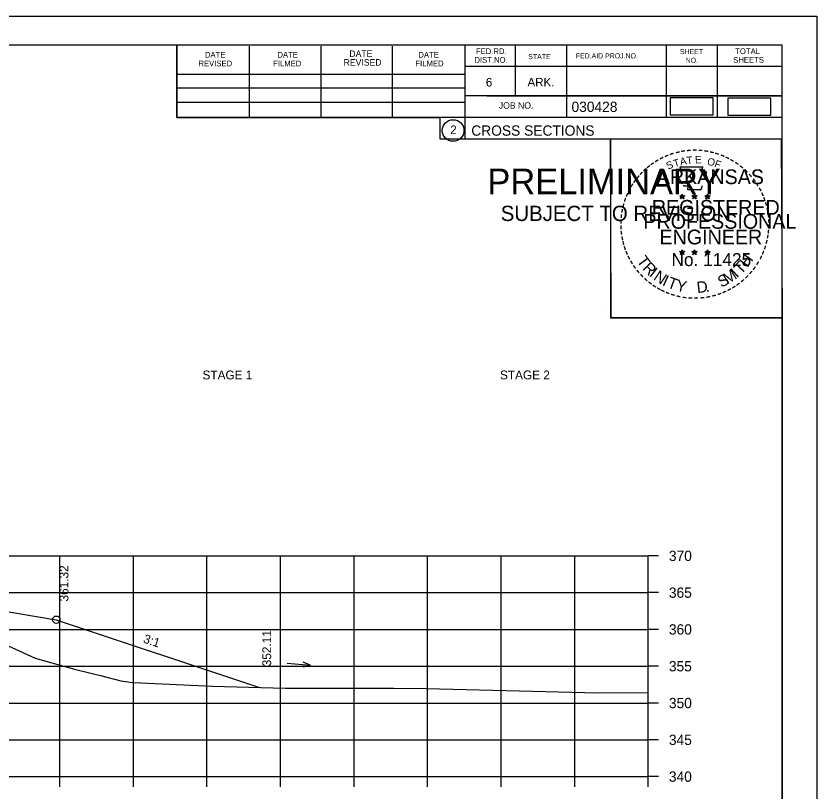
# Model space of a CAD drawing. Extents: x 1374859 to 1376773, y 382242 to 389804.
# Drawn here: x 1376188.6 to 1376297.5, y 385336.4 to 385441.8 of the extents above; entities that cross this region are included whole.
import ezdxf

# ---------------------------------------------------------------- set-up
doc = ezdxf.new("R2010")
doc.units = 0
for name, color, linetype in [('R_Axis', 7, 'Continuous'), ('R_Axis Annot', 7, 'Continuous'), ('R_Border', 7, 'Continuous'), ('R_Border PE', 7, 'Continuous'), ('R_Border Prem', 7, 'Continuous'), ('R_Exist Surface', 7, 'Continuous'), ('R_Fin Surface', 7, 'Continuous'), ('R_Grid', 7, 'Continuous'), ('R_MOT', 7, 'Continuous'), ('R_No Plot', 7, 'Continuous'), ('R_Water Annot', 7, 'Continuous'), ('R_Xsect Elev', 7, 'Continuous'), ('R_Xsect Slope', 7, 'Continuous')]:
    doc.layers.add(name, color=color, linetype=linetype)

msp = doc.modelspace()

# ---------------------------------------------------------------- linework, layer by layer
at = {"layer": 'R_Axis'}
for p, q in [((1376274.57, 385338.45), (1376274.57, 385368.45)), ((1376275.97, 385368.45), (1376274.57, 385368.45)), ((1376275.97, 385363.45), (1376274.57, 385363.45)), ((1376275.97, 385358.45), (1376274.57, 385358.45)), ((1376275.97, 385353.45), (1376274.57, 385353.45)), ((1376275.97, 385348.45), (1376274.57, 385348.45)), ((1376275.97, 385343.45), (1376274.57, 385343.45)), ((1375994.57, 385338.45), (1376274.57, 385338.45)), ((1376194.57, 385337.05), (1376194.57, 385338.45)), ((1376204.57, 385337.05), (1376204.57, 385338.45)), ((1376214.57, 385337.05), (1376214.57, 385338.45)), ((1376224.57, 385337.05), (1376224.57, 385338.45)), ((1376234.57, 385337.05), (1376234.57, 385338.45)), ((1376244.57, 385337.05), (1376244.57, 385338.45)), ((1376254.57, 385337.05), (1376254.57, 385338.45)), ((1376264.57, 385337.05), (1376264.57, 385338.45)), ((1376274.57, 385337.05), (1376274.57, 385338.45)), ((1376275.97, 385338.45), (1376274.57, 385338.45))]:
    msp.add_line(p, q, dxfattribs=at)
at = {"layer": 'R_Border'}
for p, q in [((1375976.57, 385437.91), (1376292.75, 385437.91)), ((1376210.49, 385428.03), (1376210.49, 385437.91)), ((1376220.35, 385428.03), (1376220.35, 385437.71)), ((1376230.11, 385428.03), (1376230.11, 385437.71)), ((1376239.79, 385428.03), (1376239.79, 385437.71)), ((1376249.65, 385437.91), (1376249.65, 385425.11)), ((1376256.49, 385437.91), (1376256.49, 385430.97)), ((1376263.43, 385437.91), (1376263.43, 385428.03)), ((1376277.01, 385437.91), (1376277.01, 385428.03)), ((1376283.95, 385437.91), (1376283.95, 385428.03)), ((1376292.75, 385232.45), (1376292.75, 385437.91)), ((1376292.75, 385434.97), (1376249.65, 385434.97)), ((1376292.75, 385434.99), (1376292.75, 385434.99)), ((1376210.49, 385433.89), (1376249.65, 385433.89)), ((1376210.49, 385432.03), (1376249.65, 385432.03)), ((1376292.75, 385430.97), (1376249.65, 385430.97)), ((1376252.61, 385430.97), (1376292.75, 385430.97)), ((1376210.49, 385428.03), (1376210.49, 385430.09)), ((1376210.49, 385430.09), (1376249.65, 385430.09)), ((1376292.75, 385428.03), (1376210.49, 385428.03)), ((1376249.65, 385425.11), (1376292.75, 385425.11))]:
    msp.add_line(p, q, dxfattribs=at)
msp.add_circle((1376248.04, 385426.25), 1.47, dxfattribs=at)
at = {"layer": 'R_Border PE'}
for p, q in [((1376278.84, 385417.37), (1376279.18, 385417.26)), ((1376278.84, 385417.37), (1376279.09, 385417.32)), ((1376278.84, 385417.37), (1376279.07, 385417.25)), ((1376278.97, 385416.96), (1376279.18, 385417.26)), ((1376278.97, 385416.96), (1376279.09, 385417.2)), ((1376278.97, 385416.96), (1376279.18, 385417.18)), ((1376279.18, 385417.62), (1376279.14, 385417.37)), ((1376279.18, 385417.26), (1376279.18, 385417.62)), ((1376279.18, 385417.62), (1376279.23, 385417.37)), ((1376279.53, 385417.37), (1376279.18, 385417.26)), ((1376279.4, 385416.96), (1376279.18, 385417.26)), ((1376279.4, 385416.96), (1376279.18, 385417.17)), ((1376279.53, 385417.37), (1376279.25, 385417.32)), ((1376279.4, 385416.96), (1376279.26, 385417.25)), ((1376279.53, 385417.37), (1376279.33, 385417.27)), ((1376280.51, 385417.37), (1376280.85, 385417.26)), ((1376280.51, 385417.37), (1376280.76, 385417.32)), ((1376280.51, 385417.37), (1376280.74, 385417.25)), ((1376280.64, 385416.96), (1376280.85, 385417.26)), ((1376280.64, 385416.96), (1376280.76, 385417.2)), ((1376280.64, 385416.96), (1376280.85, 385417.18)), ((1376280.85, 385417.62), (1376280.81, 385417.37)), ((1376280.85, 385417.26), (1376280.85, 385417.62)), ((1376280.85, 385417.62), (1376280.9, 385417.37)), ((1376281.2, 385417.37), (1376280.85, 385417.26)), ((1376281.07, 385416.96), (1376280.85, 385417.26)), ((1376281.07, 385416.96), (1376280.85, 385417.17)), ((1376281.2, 385417.37), (1376280.92, 385417.32)), ((1376281.07, 385416.96), (1376280.93, 385417.25)), ((1376281.2, 385417.37), (1376281, 385417.27)), ((1376282.27, 385417.36), (1376282.62, 385417.24)), ((1376282.27, 385417.36), (1376282.52, 385417.31)), ((1376282.27, 385417.36), (1376282.51, 385417.23)), ((1376282.4, 385416.95), (1376282.62, 385417.24)), ((1376282.4, 385416.95), (1376282.53, 385417.19)), ((1376282.4, 385416.95), (1376282.62, 385417.16)), ((1376282.62, 385417.61), (1376282.58, 385417.36)), ((1376282.62, 385417.24), (1376282.62, 385417.61)), ((1376282.62, 385417.61), (1376282.67, 385417.36)), ((1376282.97, 385417.36), (1376282.62, 385417.24)), ((1376282.83, 385416.95), (1376282.62, 385417.24)), ((1376282.83, 385416.95), (1376282.62, 385417.16)), ((1376282.97, 385417.36), (1376282.68, 385417.31)), ((1376282.83, 385416.95), (1376282.69, 385417.24)), ((1376282.97, 385417.36), (1376282.76, 385417.25)), ((1376279.18, 385410.05), (1376279.14, 385409.8)), ((1376279.18, 385409.68), (1376279.18, 385410.05)), ((1376279.18, 385410.05), (1376279.23, 385409.8)), ((1376280.85, 385410.05), (1376280.81, 385409.8)), ((1376280.85, 385409.68), (1376280.85, 385410.05)), ((1376280.85, 385410.05), (1376280.9, 385409.8)), ((1376282.62, 385410.04), (1376282.58, 385409.79)), ((1376282.62, 385409.67), (1376282.62, 385410.04)), ((1376282.62, 385410.04), (1376282.67, 385409.79)), ((1376278.83, 385409.79), (1376279.18, 385409.68)), ((1376278.83, 385409.79), (1376279.08, 385409.75)), ((1376278.83, 385409.79), (1376279.07, 385409.67)), ((1376278.96, 385409.39), (1376279.18, 385409.68)), ((1376278.96, 385409.39), (1376279.09, 385409.63)), ((1376278.96, 385409.39), (1376279.18, 385409.6)), ((1376279.53, 385409.79), (1376279.18, 385409.68)), ((1376279.39, 385409.39), (1376279.18, 385409.68)), ((1376279.39, 385409.39), (1376279.18, 385409.6)), ((1376279.53, 385409.79), (1376279.24, 385409.75)), ((1376279.39, 385409.39), (1376279.26, 385409.68)), ((1376279.53, 385409.79), (1376279.32, 385409.69)), ((1376280.5, 385409.79), (1376280.85, 385409.68)), ((1376280.5, 385409.79), (1376280.75, 385409.75)), ((1376280.5, 385409.79), (1376280.74, 385409.67)), ((1376280.63, 385409.39), (1376280.85, 385409.68)), ((1376280.63, 385409.39), (1376280.76, 385409.63)), ((1376280.63, 385409.39), (1376280.85, 385409.6)), ((1376281.2, 385409.79), (1376280.85, 385409.68)), ((1376281.06, 385409.39), (1376280.85, 385409.68)), ((1376281.06, 385409.39), (1376280.85, 385409.6)), ((1376281.2, 385409.79), (1376280.91, 385409.75)), ((1376281.06, 385409.39), (1376280.93, 385409.68)), ((1376281.2, 385409.79), (1376280.99, 385409.69)), ((1376282.27, 385409.78), (1376282.62, 385409.67)), ((1376282.27, 385409.78), (1376282.52, 385409.74)), ((1376282.27, 385409.78), (1376282.5, 385409.66)), ((1376282.4, 385409.38), (1376282.62, 385409.67)), ((1376282.4, 385409.38), (1376282.53, 385409.62)), ((1376282.4, 385409.38), (1376282.61, 385409.59)), ((1376282.83, 385409.38), (1376282.61, 385409.59)), ((1376282.96, 385409.78), (1376282.62, 385409.67)), ((1376282.83, 385409.38), (1376282.62, 385409.67)), ((1376282.96, 385409.78), (1376282.68, 385409.74)), ((1376282.83, 385409.38), (1376282.69, 385409.67)), ((1376282.96, 385409.78), (1376282.76, 385409.68))]:
    msp.add_line(p, q, dxfattribs=at)
for points in [[(1376278.88, 385421.25), (1376279.15, 385420.42)], [(1376282.39, 385420.32), (1376282.53, 385420.61), (1376281.84, 385420.58), (1376281.99, 385421.25), (1376278.88, 385421.25)], [(1376279.37, 385418.82), (1376279.37, 385418.74), (1376279.93, 385418.72), (1376279.88, 385418.24), (1376281.75, 385418.24), (1376281.95, 385418.78)], [(1376279.18, 385417.62), (1376279.4, 385416.96), (1376278.84, 385417.37), (1376279.53, 385417.37), (1376278.97, 385416.96), (1376279.18, 385417.62)], [(1376280.85, 385417.62), (1376281.07, 385416.96), (1376280.51, 385417.37), (1376281.2, 385417.37), (1376280.64, 385416.96), (1376280.85, 385417.62)], [(1376282.62, 385417.61), (1376282.83, 385416.95), (1376282.27, 385417.36), (1376282.97, 385417.36), (1376282.4, 385416.95), (1376282.62, 385417.61)], [(1376279.18, 385410.05), (1376279.39, 385409.39), (1376278.83, 385409.79), (1376279.53, 385409.79), (1376278.96, 385409.39), (1376279.18, 385410.05)], [(1376280.85, 385410.05), (1376281.06, 385409.39), (1376280.5, 385409.79), (1376281.2, 385409.79), (1376280.63, 385409.39), (1376280.85, 385410.05)], [(1376282.62, 385410.04), (1376282.83, 385409.38), (1376282.27, 385409.78), (1376282.96, 385409.78), (1376282.4, 385409.38), (1376282.62, 385410.04)]]:
    msp.add_lwpolyline(points, dxfattribs=at)
for centre, radius in [((1376279.18, 385417.26), 0.172), ((1376279.18, 385417.26), 0.145), ((1376279.18, 385417.26), 0.116), ((1376279.18, 385417.26), 0.0991), ((1376279.18, 385417.26), 0.0747), ((1376279.18, 385417.26), 0.0495), ((1376279.18, 385417.26), 0.0296), ((1376280.85, 385417.26), 0.172), ((1376280.85, 385417.26), 0.145), ((1376280.85, 385417.26), 0.116), ((1376280.85, 385417.26), 0.0991), ((1376280.85, 385417.26), 0.0747), ((1376280.85, 385417.26), 0.0495), ((1376280.85, 385417.26), 0.0296), ((1376282.62, 385417.24), 0.172), ((1376282.62, 385417.24), 0.145), ((1376282.62, 385417.24), 0.116), ((1376282.62, 385417.24), 0.0991), ((1376282.62, 385417.24), 0.0747), ((1376282.62, 385417.24), 0.0495), ((1376282.62, 385417.24), 0.0296), ((1376279.18, 385409.68), 0.172), ((1376279.18, 385409.68), 0.145), ((1376279.18, 385409.68), 0.116), ((1376279.18, 385409.68), 0.0991), ((1376279.18, 385409.68), 0.0747), ((1376279.18, 385409.68), 0.0495), ((1376279.18, 385409.68), 0.0296), ((1376280.85, 385409.68), 0.172), ((1376280.85, 385409.68), 0.145), ((1376280.85, 385409.68), 0.116), ((1376280.85, 385409.68), 0.0991), ((1376280.85, 385409.68), 0.0747), ((1376280.85, 385409.68), 0.0495), ((1376280.85, 385409.68), 0.0296), ((1376282.62, 385409.67), 0.172), ((1376282.62, 385409.67), 0.145), ((1376282.62, 385409.67), 0.116), ((1376282.62, 385409.67), 0.0991), ((1376282.62, 385409.67), 0.0747), ((1376282.62, 385409.67), 0.0495), ((1376282.62, 385409.67), 0.0296)]:
    msp.add_circle(centre, radius, dxfattribs=at)
at = {"layer": 'R_Exist Surface'}
msp.add_lwpolyline([(1376175.15, 385361.82), (1376189.02, 385355.56), (1376191.23, 385354.54), (1376196.57, 385353.07), (1376198.96, 385352.47), (1376200.11, 385352.19), (1376202.87, 385351.46), (1376204.15, 385351.28), (1376204.59, 385351.24), (1376215.33, 385350.75), (1376225.21, 385350.47), (1376239.93, 385350.46), (1376244.36, 385350.44), (1376258.82, 385350.05), (1376267.71, 385349.83), (1376274.57, 385349.87)], dxfattribs=at)
at = {"layer": 'R_Fin Surface'}
msp.add_lwpolyline([(1376045.72, 385350.21), (1376053.8, 385347.51), (1376075.09, 385354.61), (1376084.29, 385356.14), (1376097.09, 385358.27), (1376105.09, 385358.82), (1376134.59, 385360.86), (1376164.09, 385362.89), (1376172.09, 385363.44), (1376185.45, 385361.21), (1376194.09, 385359.77), (1376221.71, 385350.57)], dxfattribs=at)
at = {"layer": 'R_Grid'}
for p, q in [((1375994.57, 385368.45), (1376274.57, 385368.45)), ((1376194.57, 385338.45), (1376194.57, 385368.45)), ((1376204.57, 385338.45), (1376204.57, 385368.45)), ((1376214.57, 385338.45), (1376214.57, 385368.45)), ((1376224.57, 385338.45), (1376224.57, 385368.45)), ((1376234.57, 385338.45), (1376234.57, 385368.45)), ((1376244.57, 385338.45), (1376244.57, 385368.45)), ((1376254.57, 385338.45), (1376254.57, 385368.45)), ((1376264.57, 385338.45), (1376264.57, 385368.45)), ((1376274.57, 385338.45), (1376274.57, 385368.45)), ((1375994.57, 385363.45), (1376274.57, 385363.45)), ((1375994.57, 385358.45), (1376274.57, 385358.45)), ((1375994.57, 385353.45), (1376274.57, 385353.45)), ((1375994.57, 385348.45), (1376274.57, 385348.45)), ((1375994.57, 385343.45), (1376274.57, 385343.45)), ((1375994.57, 385338.45), (1376274.57, 385338.45))]:
    msp.add_line(p, q, dxfattribs=at)
at = {"layer": 'R_MOT'}
for points in [[(1376277.55, 385428.37), (1376283.38, 385428.37), (1376283.38, 385430.68), (1376277.55, 385430.68)], [(1376285.38, 385428.35), (1376291.21, 385428.35), (1376291.21, 385430.66), (1376285.38, 385430.66)]]:
    msp.add_lwpolyline(points, close=True, dxfattribs=at)
at = {"layer": 'R_No Plot'}
for p, q in [((1375964.17, 385441.81), (1376297.5, 385441.81)), ((1376268.78, 385402.66), (1376268.78, 385402.66))]:
    msp.add_line(p, q, dxfattribs=at)
for points in [[(1375964.16, 385441.81), (1376297.5, 385441.81), (1376297.5, 385228.47), (1375964.16, 385228.47)], [(1376210.49, 385437.91), (1376210.49, 385428.03), (1376246.22, 385428.03), (1376246.22, 385425.11), (1376269.42, 385425.11), (1376269.42, 385400.78), (1376292.75, 385400.78), (1376292.75, 385232.45), (1375976.57, 385232.45), (1375976.57, 385437.91)], [(1376269.42, 385425.11), (1376292.63, 385425.11), (1376292.75, 385400.78), (1376269.54, 385400.78)]]:
    msp.add_lwpolyline(points, close=True, dxfattribs=at)
msp.add_circle((1376194.09, 385359.77), 0.5, dxfattribs=at)
at = {"layer": 'R_Water Annot'}
for p, q in [((1376225.46, 385353.88), (1376228.59, 385353.58)), ((1376228.59, 385353.58), (1376227.6, 385353.32)), ((1376228.59, 385353.58), (1376227.67, 385354.02))]:
    msp.add_line(p, q, dxfattribs=at)

# ---------------------------------------------------------------- texts
at = {"layer": 'R_Axis Annot'}
for s, p in [('STAGE 1', (1376213.97, 385392.43)), ('STAGE 2', (1376254.41, 385392.43))]:
    msp.add_text(s, height=1.2, rotation=360, dxfattribs=at).set_placement(p)
for s, p in [('370', (1376277.37, 385367.75)), ('365', (1376277.37, 385362.75)), ('360', (1376277.37, 385357.75)), ('355', (1376277.37, 385352.75)), ('350', (1376277.37, 385347.75)), ('345', (1376277.37, 385342.75)), ('340', (1376277.37, 385337.75))]:
    msp.add_text(s, height=1.4, dxfattribs=at).set_placement(p)
at = {"layer": 'R_Border'}
for s, height, p in [('FED.RD.', 0.782, (1376251.13, 385436.63)), ('SHEET', 0.684, (1376278.87, 385436.63)), ('TOTAL', 0.782, (1376286.39, 385436.63)), ('DATE', 0.782, (1376214.29, 385436.15)), ('DATE', 0.782, (1376224.15, 385436.15)), ('DATE', 0.879, (1376233.93, 385436.25)), ('DATE', 0.782, (1376243.31, 385436.15)), ('DIST.NO.', 0.782, (1376250.93, 385435.45)), ('STATE', 0.684, (1376258.25, 385435.95)), ('FED.AID PROJ.NO.', 0.684, (1376264.71, 385436.05)), ('NO.', 0.684, (1376279.65, 385435.45)), ('SHEETS', 0.782, (1376286.11, 385435.45)), ('REVISED', 0.782, (1376213.41, 385434.97)), ('FILMED', 0.782, (1376223.57, 385434.97)), ('REVISED', 0.879, (1376233.15, 385435.07)), ('FILMED', 0.782, (1376242.91, 385434.97)), ('6', 1.17, (1376252.49, 385432.23)), ('ARK.', 1.172, (1376258.15, 385432.23)), ('JOB NO.', 0.879, (1376254.25, 385429.21)), ('030428', 1.4, (1376264.13, 385428.77)), ('2', 1.17, (1376247.65, 385425.76)), ('CROSS SECTIONS', 1.4, (1376250.51, 385425.54))]:
    msp.add_text(s, height=height, rotation=360, dxfattribs=at).set_placement(p)
at = {"layer": 'R_Border PE'}
for s, height, rotation, p in [('-', 1.6, 19.1761, (1376277.62, 385422.37)), ('-', 1.6, 13.6301, (1376278.37, 385422.61)), ('-', 1.6, 10.2193, (1376279.05, 385422.78)), ('-', 1.6, 5.8968, (1376279.78, 385422.89)), ('-', 1.6, 0.1862, (1376280.55, 385422.96)), ('-', 1.6, 357.743, (1376281.28, 385422.94)), ('-', 1.6, 352.1617, (1376282.02, 385422.89)), ('-', 1.6, 347.2049, (1376282.74, 385422.77)), ('-', 1.6, 342.3362, (1376283.37, 385422.62)), ('-', 1.6, 34.0636, (1376275.76, 385421.42)), ('-', 1.6, 28.7918, (1376276.36, 385421.79)), ('-', 1.6, 24.3072, (1376276.99, 385422.1)), ('S', 1, 21.594, (1376277.23, 385420.92)), ('T', 1, 16.4036, (1376278.15, 385421.25)), ('A', 1, 11.2132, (1376278.97, 385421.51)), ('T', 1, 6.0228, (1376279.82, 385421.67)), ('E', 1, 0.8323, (1376280.93, 385421.78)), ('O', 1, 350.4515, (1376282.53, 385421.57)), ('F', 1, 340.0707, (1376283.48, 385421.34)), ('-', 1.6, 337.8551, (1376284.11, 385422.4)), ('-', 1.6, 334.1211, (1376284.74, 385422.13)), ('-', 1.6, 329.6409, (1376285.32, 385421.84)), ('-', 1.6, 325.8627, (1376285.96, 385421.48)), ('-', 1.6, 42.9622, (1376274.27, 385420.23)), ('-', 1.6, 38.9507, (1376274.71, 385420.64)), ('-', 1.6, 36.2317, (1376275.18, 385421.02)), ('ARKANSAS', 2, 360, (1376275.73, 385418.96)), ('-', 1.6, 320.5297, (1376286.57, 385421.06)), ('-', 1.6, 315.5786, (1376287.17, 385420.57)), ('-', 1.6, 50.6142, (1376273.42, 385419.26)), ('-', 1.6, 48.423, (1376273.83, 385419.75)), ('-', 1.6, 309.8797, (1376287.74, 385420.02)), ('-', 1.6, 58.0706, (1376272.68, 385418.17)), ('-', 1.6, 54.2325, (1376273.01, 385418.7)), ('-', 1.6, 306.6522, (1376288.27, 385419.42)), ('-', 1.4, 303.6753, (1376288.75, 385418.85)), ('-', 1.6, 67.7743, (1376272.11, 385416.94)), ('-', 1.6, 62.8713, (1376272.37, 385417.55)), ('-', 1.6, 299.6684, (1376289.07, 385418.24)), ('-', 1.6, 294.6628, (1376289.39, 385417.63)), ('-', 1.6, 72.3945, (1376271.89, 385416.31)), ('REGISTERED', 2, 360, (1376275.05, 385414.81)), ('DWB', 0.01, 360, (1376279.17, 385417.25)), ('DWB', 0.01, 360, (1376280.84, 385417.25)), ('DWB', 0.01, 360, (1376282.61, 385417.24)), ('-', 1.6, 290.5728, (1376289.65, 385417.05)), ('-', 1.6, 285.1233, (1376289.89, 385416.47)), ('-', 1.6, 81.2013, (1376271.56, 385414.89)), ('-', 1.6, 75.461, (1376271.7, 385415.6)), ('-', 1.6, 280.5493, (1376290.09, 385415.73)), ('-', 1.6, 85.1863, (1376271.49, 385414.2)), ('PROFESSIONAL', 2, 360, (1376273.9, 385412.9)), ('-', 1.6, 276.5962, (1376290.25, 385414.96)), ('-', 1.6, 94.1959, (1376271.5, 385412.77)), ('-', 1.6, 89.0622, (1376271.46, 385413.49)), ('-', 1.6, 274.3301, (1376290.31, 385414.24)), ('-', 1.6, 269.9407, (1376290.34, 385413.61)), ('-', 1.6, 98.9479, (1376271.57, 385412.1)), ('ENGINEER', 2, 360, (1376276.09, 385410.78)), ('-', 1.6, 263.5172, (1376290.32, 385412.94)), ('-', 1.6, 101.7149, (1376271.71, 385411.37)), ('-', 1.6, 105.4578, (1376271.87, 385410.77)), ('-', 1.6, 255.7626, (1376290.14, 385411.61)), ('-', 1.6, 260.9953, (1376290.25, 385412.29)), ('-', 1.6, 109.0874, (1376272.08, 385410.14)), ('-', 1.6, 252.8681, (1376289.96, 385410.89)), ('-', 1.6, 114.0643, (1376272.34, 385409.55)), ('-', 1.6, 115.7289, (1376272.64, 385408.93)), ('T', 1.54, 306.0406, (1376272.94, 385408.52)), ('No. 11425', 1.757, 360, (1376277.72, 385407.83)), ('DWB', 0.01, 360, (1376279.17, 385409.68)), ('DWB', 0.01, 360, (1376280.84, 385409.68)), ('DWB', 0.01, 360, (1376282.6, 385409.67)), ('H', 1.54, 54.6088, (1376288.06, 385407.56)), ('-', 1.6, 244.6197, (1376289.48, 385409.59)), ('-', 1.6, 247.8887, (1376289.74, 385410.22)), ('-', 1.6, 120.4471, (1376273, 385408.34)), ('-', 1.6, 125.8934, (1376273.4, 385407.78)), ('R', 1.54, 314.005, (1376273.7, 385407.47)), ('T', 1.54, 46.6444, (1376287.17, 385406.61)), ('-', 1.6, 239.0712, (1376289.08, 385408.84)), ('-', 1.6, 130.7181, (1376273.86, 385407.23)), ('-', 1.6, 134.2238, (1376274.38, 385406.69)), ('I', 1.54, 321.9694, (1376274.6, 385406.54)), ('N', 1.54, 326.5002, (1376275.17, 385406.07)), ('M', 1.54, 32.6563, (1376285.32, 385405.29)), ('I', 1.54, 42.1136, (1376286.61, 385406.14)), ('-', 1.6, 231.2538, (1376288.25, 385407.62)), ('-', 1.6, 233.8452, (1376288.68, 385408.18)), ('-', 1.6, 138.9338, (1376274.91, 385406.22)), ('-', 1.6, 144.6463, (1376275.46, 385405.82)), ('I', 1.54, 335.3603, (1376276.38, 385405.28)), ('T', 1.54, 339.8912, (1376277.04, 385404.96)), ('Y', 1.54, 347.8556, (1376278.26, 385404.51)), ('D', 1.54, 6.3969, (1376281.24, 385404.15)), ('S', 1.54, 26.9312, (1376284.49, 385404.88)), ('-', 1.6, 221.0851, (1376287.25, 385406.54)), ('-', 1.6, 225.7653, (1376287.77, 385407.05)), ('-', 1.6, 148.0898, (1376276.02, 385405.44)), ('-', 1.6, 151.5704, (1376276.6, 385405.12)), ('-', 1.6, 154.6002, (1376277.12, 385404.87)), ('.', 1.54, 13.7642, (1376282.43, 385404.28)), ('-', 1.6, 207.3568, (1376285.61, 385405.34)), ('-', 1.6, 212.2491, (1376286.17, 385405.68)), ('-', 1.6, 215.7363, (1376286.7, 385406.07)), ('-', 1.6, 158.5612, (1376277.75, 385404.62)), ('-', 1.6, 162.7983, (1376278.43, 385404.41)), ('-', 1.6, 167.5555, (1376279.15, 385404.24)), ('-', 1.6, 173.1155, (1376279.92, 385404.13)), ('-', 1.6, 176.5183, (1376280.67, 385404.08)), ('-', 1.6, 181.5918, (1376281.41, 385404.1)), ('-', 1.6, 185.8167, (1376282.22, 385404.17)), ('-', 1.6, 191.2858, (1376282.96, 385404.31)), ('-', 1.6, 195.4743, (1376283.69, 385404.5)), ('-', 1.6, 200.7184, (1376284.36, 385404.75)), ('-', 1.6, 204.2516, (1376284.98, 385405.02))]:
    msp.add_text(s, height=height, rotation=rotation, dxfattribs=at).set_placement(p)
at = {"layer": 'R_Border Prem'}
for s, height, p in [('PRELIMINARY', 3.5, (1376252.7, 385417.58)), ('DWB', 0.01, (1376253.45, 385419.42)), ('SUBJECT TO REVISION', 2.0751, (1376254.51, 385413.95))]:
    msp.add_text(s, height=height, rotation=360, dxfattribs=at).set_placement(p)
at = {"layer": 'R_Xsect Elev'}
for s, p in [('361.32', (1376195.74, 385362.25)), ('352.11', (1376223.3, 385353.44))]:
    msp.add_text(s, height=1.2, rotation=90, dxfattribs=at).set_placement(p)
at = {"layer": 'R_Xsect Slope'}
msp.add_text('3:1', height=1.2, rotation=341.5651, dxfattribs=at).set_placement((1376205.83, 385356.69))

doc.saveas('drawing.dxf')
